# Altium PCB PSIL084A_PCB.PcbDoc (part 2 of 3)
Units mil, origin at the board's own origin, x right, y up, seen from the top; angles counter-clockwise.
Board outline 8750 x 2700 mil, 4 copper layers (Top Layer, Signal Layer 1, Signal Layer 2, Bottom Layer), stack 61.2 mil thick; 274 components, 214 nets, 1279 pads, 354 vias.
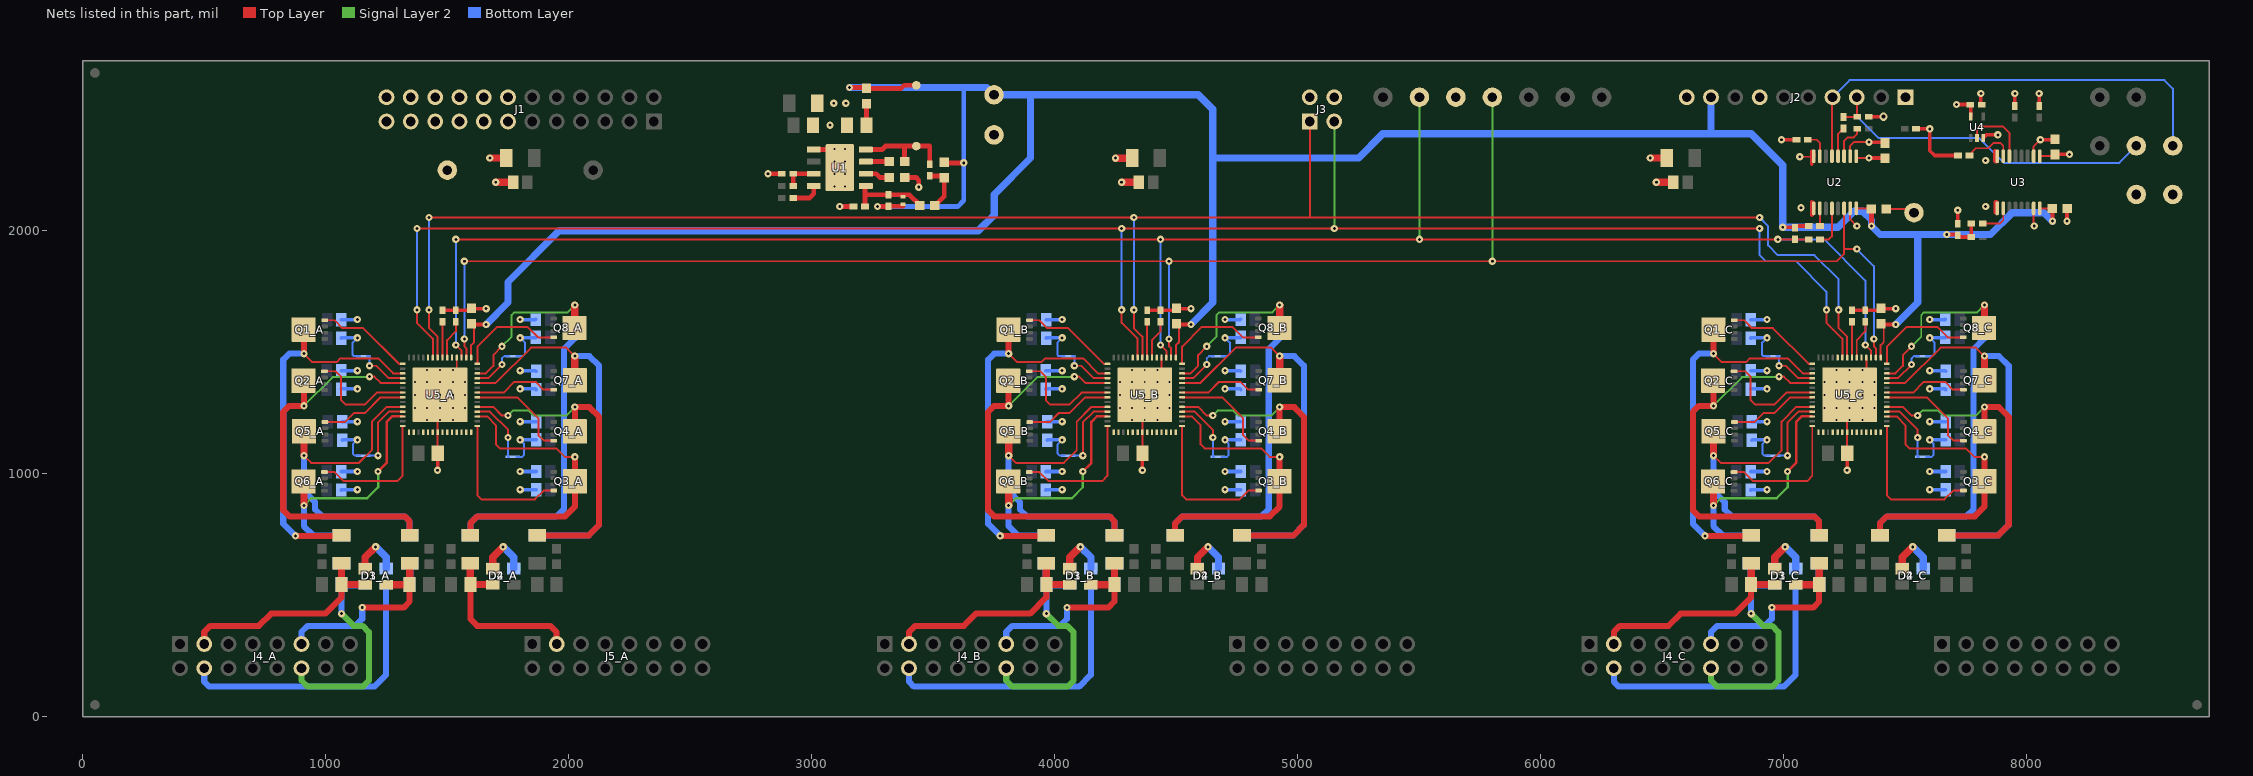
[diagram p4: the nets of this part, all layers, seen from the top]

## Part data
C1: library part CMP-0750039-1, "CAP, CERM, 0.01 µF, 50 V,+/- 10%, X7R, 0603", Cap_Case=0603, Manufacturer="Wurth Elektronik", TempCo=X7R, Tolerance_%=10%, Value2=50V, ValueDisplayed=0.01µF
C2: library part CMP-0007210-4, "CAP, CERM, 3300 pF, 50 V, +/- 5%, C0G/NP0, 0603", Cap_Case=0603, Manufacturer=MuRata, Supplier Part Number 1=GRM1885C1H332JA01D-ND, TempCo=C0G/NP0, Tolerance_%=5%, Value1=Unknown, Value2=50V, ValueDisplayed=3300pF
C3: library part CMP-0086511-1, "120pF ±1% 50V Ceramic Capacitor C0G, NP0 0402 (1005 Metric)", Manufacturer=Murata, TempCo=30ppm/°C, Tolerance_%=1%
C4 C17_A C17_B C17_C C18 C20_A C20_B C20_C C21_A C21_B C21_C C22_A C22_B C22_C C23_A C23_B C23_C C24_A C24_B C24_C C25_A C25_B C25_C C26_A C26_B C26_C C27_A C27_B C27_C C28 C30: library part CMP-0007886-2, "CAP, CERM, 0.1 uF, 100 V, +/- 10%, X7R, 0805", Cap_Case=0805, Manufacturer=TDK, Supplier Part Number 1=445-1418-1-ND, TempCo=X7R, Tolerance_%=10%, Value1="0.020726 ohm", Value2=100V, ValueDisplayed=0.1uF
C5 C9 C10 C11 C12 C16_A C16_B C16_C: library part CMP-0006837-4, "CAP, CERM, 0.1 uF, 50 V, +/- 10%, X7R, 0603", Cap_Case=0603, Manufacturer="Wurth Elektronik", TempCo=X7R, Tolerance_%=10%, Value1=Unknown, Value2=50V, ValueDisplayed=0.1uF
C6 C15 C19 C29: library part CMP-0750040-1, "CAP, CERM, 1 µF, 100 V,+/- 10%, X7R, AEC-Q200 Grade 1, 1206", Cap_Case=1206, Manufacturer=MuRata, TempCo=X7R, Tolerance_%=10%, Value2=100V, ValueDisplayed=1µF
C7: library part CMP-0007691-2, "CAP, CERM, 10 uF, 10 V, +/- 10%, X7R, 0805", Cap_Case=0805, Manufacturer="Wurth Elektronik", Supplier Part Number 1=710-885012207026, TempCo=X7R, Tolerance_%=10%, Value1=Unknown, Value2=10V, ValueDisplayed=10uF
C8: library part CMP-0082012-1, "CAP, CERM, 1 µF, 16 V,+/- 20%, X7R, 0603", Cap_Case=0603, Manufacturer=Samsung, Supplier Part Number 1=1276-6524-1-ND, TempCo=X7R, Tolerance_%=20%, Value2=16V, ValueDisplayed=1µF
C13 C14: library part CMP-0006227-2, "CAP, CERM, 0.01 uF, 16 V, +/- 10%, X7R, 0402", Cap_Case=0402, Manufacturer="Wurth Elektronik", Supplier Part Number 1=710-885012205031, TempCo=X7R, Tolerance_%=10%, Value1=Unknown, Value2=16V, ValueDisplayed=0.01uF
D1_A D1_B D1_C D2_A D2_B D2_C D3_A D3_B D3_C D4_A D4_B D4_C: library part CMP-0002018-2, "ESD Suppressor Diode Arrays, 7V, SMD", Manufacturer=Bourns, Supplier Part Number 1=CD143A-SR70CT-ND
F1_A F1_B F1_C F2_A F2_B F2_C F3_A F3_B F3_C F4_A F4_B F4_C F5_A F5_B F5_C F6_A F6_B F6_C F7_A F7_B F7_C F8_A F8_B F8_C: library part CMP-0003587-2, "Fuse, 1.5 A, 63VAC/VDC, SMD", Irating_A=1.5A, Manufacturer="Bel Fuse", Supplier Part Number 1=507-1188-1-ND
FID1 FID2 FID3 FID4 FID5 FID6: library part CMP-0077181-1, "Fiducial mark.  There is nothing to buy or mount.", Manufacturer=N/A
J1: library part CMP-0075423-1, "Header, 100mil, 12x2, Gold, TH", Color=Black, Current_A=6.3A, Manufacturer=Samtec, Supplier Part Number 1=SAM1028-12-ND, Voltage_V=550V
J2: library part CMP-0075422-1, "Header, 100mil, 10x1, Gold, TH", Color=Black, Current_A=6.3A, Manufacturer=Samtec, Supplier Part Number 1=SAM1029-10-ND, Voltage_V=550V
J3: library part CMP-0075404-1, "Header, 100mil, 2x2, Gold, TH", Color=Black, Current_A=6.3A, Manufacturer=Samtec, Supplier Part Number 1=SAM1028-02-ND, Voltage_V=550V
J4_A J4_B J4_C J5_A J5_B J5_C: library part CMP-0075418-1, "Header, 100mil, 8x2, Gold, TH", Color=Black, Current_A=6.3A, Manufacturer=Samtec, Supplier Part Number 1=SAM1028-08-ND, Voltage_V=550V
L1: library part CMP-0064704-3, "Inductor, Shielded Drum Core, Ferrite, 150 uH, 0.36 A, 0.605 ohm, SMD", Manufacturer="Wurth Elektronik", Supplier Part Number 1=732-3679-1-ND, Value1="0.605 ohm", Value2=0.36A, ValueDisplayed=150uH
L2_A L2_B L2_C L3_A L3_B L3_C L4_A L4_B L4_C L5_A L5_B L5_C L6_A L6_B L6_C L7_A L7_B L7_C L8_A L8_B L8_C L9_A L9_B L9_C: library part CMP-0078795-1, "Ferrite Bead, 600 ohm @ 100 MHz, 1 A, 0603", Manufacturer=TDK, Supplier Part Number 1=445-172898-1-ND, Value1="0.15 ohm", Value2=1A, ValueDisplayed="600 ohm"
LBL1: library part CMP-0003625-1, "Thermal Transfer Printable Labels, 0.650\" W x 0.200\" H - 10,000 per roll", Manufacturer=Brady, Supplier Part Number 1=97C5133
Logo1: library part CMP-0074838-1, "Texas Instrument Corporate Signature"
Logo2: library part CMP-0074844-1
Logo3: library part CMP-0074847-1, "FCC_disclaimer"
Logo4: library part CMP-0074769-1
NT_A1_A NT_A1_B NT_A1_C NT_B1_A NT_B1_B NT_B1_C NT_C1_A NT_C1_B NT_C1_C NT_D1_A NT_D1_B NT_D1_C: library part CMP-0078142-2, "Single point connection between nets.", Manufacturer=N/A
Q1_A Q1_B Q1_C Q2_A Q2_B Q2_C Q3_A Q3_B Q3_C Q4_A Q4_B Q4_C Q5_A Q5_B Q5_C Q6_A Q6_B Q6_C Q7_A Q7_B Q7_C Q8_A Q8_B Q8_C: library part CMP-0000969-3, "MOSFET, N-CH, 100 V, 5 A, DNH0008A (VSONP-8)", Alternate Manufacturer=None, Manufacturer="Texas Instruments", Value2="7.2 nC"
R1: library part CMP-0026021-3, "RES, 150 k, 1%, 0.063 W, AEC-Q200 Grade 0, 0402", Manufacturer=Vishay-Dale, Power_W=63mW, Supplier Part Number 1=541-150KLCT-ND, TempCo="100 ppm/C", Tolerance_%=1%, Value2=0.063W, Value_Code=150k
R2: library part CMP-0025950-3, "RES, 100 k, 1%, 0.063 W, AEC-Q200 Grade 0, 0402", Manufacturer=Vishay-Dale, Power_W=63mW, Supplier Part Number 1=541-100KLCT-ND, TempCo="100 ppm/C", Tolerance_%=1%, Value2=0.063W, Value_Code=100k
R3 R8 R14 R17 R18: library part CMP-0025958-3, "RES, 10.0 k, 1%, 0.063 W, AEC-Q200 Grade 0, 0402", Manufacturer=Vishay-Dale, Power_W=63mW, Supplier Part Number 1=541-10.0KLCT-ND, TempCo="100 ppm/C", Tolerance_%=1%, Value2=0.063W, Value_Code=10k0, ValueDisplayed=10.0k
R4: library part CMP-0025999-3, "RES, 133 k, 1%, 0.063 W, AEC-Q200 Grade 0, 0402", Manufacturer=Vishay-Dale, Power_W=63mW, Supplier Part Number 1=541-133KLCT-ND, TempCo="100 ppm/C", Tolerance_%=1%, Value2=0.063W, Value_Code=133k
R5: library part CMP-0025885-5, "RES, 0, 5%, 0.1 W, 0603", Manufacturer=Yageo, Power_W=100mW, Supplier Part Number 1=311-0.0GRCT-ND, TempCo="200 ppm/C", Tolerance_%=5%, Value2=0.1W, Value_Code=0000, ValueDisplayed=0
R6: library part CMP-0026340-2, "RES, 3.92 k, 1%, 0.063 W, AEC-Q200 Grade 0, 0402", Manufacturer=Vishay-Dale, Power_W=63mW, Supplier Part Number 1=541-3.92KLCT-ND, TempCo="100 ppm/C", Tolerance_%=1%, Value2=0.063W, Value_Code=3k92, ValueDisplayed=3.92k
R7: library part CMP-0026512-2, "RES, 6.04 k, 1%, 0.063 W, AEC-Q200 Grade 0, 0402", Manufacturer=Vishay-Dale, Power_W=63mW, Supplier Part Number 1=541-6.04KLCT-ND, TempCo="100 ppm/C", Tolerance_%=1%, Value2=0.063W, Value_Code=6k04, ValueDisplayed=6.04k
R9 R13 R15 R16 R37 R38: library part CMP-0026938-5, "RES, 4.7 k, 5%, 0.063 W, AEC-Q200 Grade 0, 0402", Manufacturer=Vishay-Dale, Power_W=63mW, Supplier Part Number 1=541-4.7KJCT-ND, TempCo="200 ppm/C", Tolerance_%=5%, Value2=0.063W, Value_Code=4k70, ValueDisplayed=4.7k
R10 R11 R12 R19_A R19_B R19_C R20_A R20_B R20_C: library part CMP-0026992-3, "RES, 0, 5%, 0.1 W, AEC-Q200 Grade 0, 0402", Manufacturer=Panasonic, Power_W=100mW, Supplier Part Number 1=P0.0JCT-ND, TempCo="600 ppm/C", Tolerance_%=5%, Value2=0.1W, Value_Code=0000, ValueDisplayed=0
R21_A R21_B R21_C R22_A R22_B R22_C R23_A R23_B R23_C R24_A R24_B R24_C R25_A R25_B R25_C R26_A R26_B R26_C R27_A R27_B R27_C R28_A R28_B R28_C R29_A R29_B R29_C R30_A R30_B R30_C R31_A R31_B R31_C R32_A R32_B R32_C R33_A R33_B R33_C R34_A R34_B R34_C R35_A R35_B R35_C R36_A R36_B R36_C: library part CMP-0021516-2, "RES, 0.51, 1%, 0.25 W, 0805", Manufacturer=Bourns, Power_W=250mW, Supplier Part Number 1=652-CRM0805FXR510ELF, TempCo="100 ppm/C", Tolerance_%=1%, Value2=0.25W, Value_Code=R510, ValueDisplayed=0.51
SH-J1 SH-J2: library part CMP-0003642-1, "Shunt, 100mil, Flash Gold, Black", Manufacturer="Sullins Connector Solutions", Supplier Part Number 1=S9001-ND
TP1 TP2 TP5: library part CMP-0055137-1, "Test Point, Miniature, Red, TH", Color=Red, Manufacturer=Keystone, PartNumber=5000, Supplier Part Number 1=36-5000-ND
TP3 TP4 TP14 TP15 TP19: library part CMP-0055138-1, "Test Point, Miniature, Black, TH", Color=Black, Manufacturer=Keystone, PartNumber=5001, Supplier Part Number 1=36-5001-ND
TP6 TP7 TP8 TP9 TP10: library part CMP-0055140-1, "Test Point, Miniature, Orange, TH", Color=Orange, Manufacturer=Keystone, PartNumber=5003, Supplier Part Number 1=36-5003-ND
TP11 TP12 TP13 TP16 TP17 TP18: library part CMP-0055139-1, "Test Point, Miniature, White, TH", Color=White, Manufacturer=Keystone, PartNumber=5002, Supplier Part Number 1=36-5002-ND
U1: library part CMP-0066086-2, "7.5-100V Wide Vin, 600mA Constant On-Time Synchronous Buck Regulator, DDA0008B (SOIC-8)", Alternate Manufacturer="Texas Instruments", Alternate PartNumber=LM5017MR/NOPB
U2: library part CMP-0078720-1, "High Speed, Robust EMC Triple-Channel Digital Isolators, DBQ0016A (SSOP-16)", Alternate Manufacturer="Texas Instruments", Alternate PartNumber=ISO7731FDBQR
U3: library part CMP-0013040-3, "High Speed, Robust EMC Quad-Channel Digital Isolators, DBQ0016A (SSOP-16)", Alternate Manufacturer="Texas Instruments", Alternate PartNumber=ISO7741DBQ
U4: library part CMP-0051390-2, "Single Buffer/Driver With Open-Drain Output, DCK0005A, LARGE T&R", F @ Nom Voltage(Max)(Mhz)=150, Generic Part Number=SN74LVC1G07, ICC @ Nom Voltage(Max)(mA)=0.01, Manufacturer="Texas Instruments", Operating Temperature Range(C)="-40 to 125,-40 to 85", Rating=Catalog, tpd @ Nom Voltage(Max)(ns)=8.6,6,4.7,4, Voltage(Nom)(V)=1.8,2.5,3.3,5
U5_A U5_B U5_C: library part CMP-0014018-5, "IEEE 802.3at 8-Port Power-over-Ethernet PSE, RTQ0056E (VQFN-56)", Alternate Manufacturer="Texas Instruments", Alternate PartNumber=TPS2388RTQT
ZZ1: library part CMP-0003616-3
ZZ2: library part CMP-0077236-1
ZZ3: library part CMP-0077237-1
ZZ4: library part CMP-0077238-1
ZZ5: library part CMP-0077238-1, "DO NOT TRIM CONNECTOR PINS on J5"

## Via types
v1: diameter 30, hole 12, Top Layer to Bottom Layer, 282 vias
v2: diameter 19.68, hole 7.87, Top Layer to Bottom Layer, 67 vias
v3: diameter 19.68, hole 7.87, Top Layer to Bottom Layer, tented both sides, 4 vias
v4: diameter 34, hole 16, Top Layer to Bottom Layer, 1 vias

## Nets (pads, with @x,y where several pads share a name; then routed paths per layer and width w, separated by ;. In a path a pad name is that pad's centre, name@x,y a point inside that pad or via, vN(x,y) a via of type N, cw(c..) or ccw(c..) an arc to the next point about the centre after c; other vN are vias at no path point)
3.3V_ISO: C9.1 C11.1 C14.2 J2.1 R8.1 R13.2 R17.1 R18.1 R38.2 TP5.1 U2.1 U3.1 U4.5 | length 796.1
  Top Layer w8: U2.1@7297.5,2307.28 7297.5,2302.5 7300,2300 v1(7350,2300) ; U3.1@8052.5,2307.28 8108.11,2307.28 C11.1@8115,2314.17
  Top Layer w15: v1(6990,2375) R13.2@7051.38,2375 ; v1(7350,2300) 7413.5,2300 C9.1@7415,2298.5 ; R8.1@7543.62,2420 v1(7600,2420) 7600,2330 7620,2310 R38.2@7720.31,2310 ; v1(7710,2520) 7766.31,2520 7768.82,2517.49 U4.5@7768.82,2470 ; R17.1@7950,2513.62 v1(7950,2565) ; R18.1@8050,2513.62 v1(8050,2565) ; C11.1@8115,2314.17 8115.83,2315 v1(8175,2315)
\PSE_INT: R9.1 R12.2 TP13.1 U5_A.45 U5_B.45 U5_C.45 | length 7900.5
  Top Layer w8: v1(1535,1530) 1558.58,1506.42 U5_A.45@1558.58,1478.54 ; v1(1535,1965) v1(4435,1965) v1(5500,1965) v1(6975,1965) R9.1@7045,1965 R12.2@7101.38,1965 ; v1(4435,1530) 4458.58,1506.42 U5_B.45@4458.58,1478.54 ; v1(7335,1530) 7358.58,1506.42 U5_C.45@7358.58,1478.54
  Signal Layer 2 w8: v1(5500,1965) TP13.1@5500,2550
  Bottom Layer w8: v1(1535,1530) v1(1535,1965) ; v1(4435,1530) v1(4435,1965) ; v1(6975,1965) 7165,1965 7335,1795 v1(7335,1530)
\PSE_RESET_A: TP11.1 U2.14 U5_A.44 U5_B.44 U5_C.44 | length 7883.8
  Top Layer w8: v1(1570,1555) 1570,1525 1578.27,1516.73 U5_A.44@1578.27,1478.54 ; v1(1570,1875) v1(4470,1875) v1(5800,1875) 7217.5,1875 7247.5,1905 7247.5,1925 ; v1(4470,1555) 4470,1525 4478.27,1516.73 U5_B.44@4478.27,1478.54 ; U2.14@7247.5,2092.72 7247.5,1925 ; v1(7300,1925) 7247.5,1925 ; v1(7370,1555) 7370,1525 7378.27,1516.73 U5_C.44@7378.27,1478.54
  Signal Layer 2 w8: v1(5800,1875) TP11.1@5800,2550
  Bottom Layer w8: v1(1570,1555) v1(1570,1875) ; v1(4470,1555) v1(4470,1875) ; v1(7300,1925) 7370,1855 v1(7370,1555)
GND: C4.1 C6.1 C7.2 C8.2 C10.2 C12.2 C13.1 C15.1 C16_A.2 C16_B.2 C16_C.2 C17_A.2 C17_B.2 C17_C.2 C18.1 C19.1 C28.1 C29.1 C30.1 D1_A.1 D1_B.1 D1_C.1 D2_A.1 D2_B.1 D2_C.1 D3_A.1 D3_B.1 D3_C.1 D4_A.1 D4_B.1 D4_C.1 J1.13 J1.14 J1.15 J1.16 J1.17 J1.18 J1.19 J1.20 J1.21 J1.22 J1.23 J1.24 J2.10 J3.2 J3.4 NT_A1_A.1 NT_A1_B.1 NT_A1_C.1 NT_B1_A.2 NT_B1_B.2 NT_B1_C.2 NT_C1_A.2 NT_C1_B.2 NT_C1_C.2 NT_D1_A.2 NT_D1_B.2 NT_D1_C.2 R6.2 R7.2 R19_A.2 R19_B.2 R19_C.2 R20_A.2 R20_B.2 R20_C.2 R21_A.2 R21_B.2 R21_C.2 R22_A.2 R22_B.2 R22_C.2 R23_A.2 R23_B.2 R23_C.2 R24_A.2 R24_B.2 R24_C.2 R25_A.2 R25_B.2 R25_C.2 R26_A.2 R26_B.2 R26_C.2 R27_A.2 R27_B.2 R27_C.2 R28_A.2 R28_B.2 R28_C.2 R29_A.2 R29_B.2 R29_C.2 R30_A.2 R30_B.2 R30_C.2 R31_A.2 R31_B.2 R31_C.2 R32_A.2 R32_B.2 R32_C.2 R33_A.2 R33_B.2 R33_C.2 R34_A.2 R34_B.2 R34_C.2 R35_A.2 R35_B.2 R35_C.2 R36_A.2 R36_B.2 R36_C.2 TP3.1 TP4.1 TP14.1 TP19.1 U1.1 U1.9@3115,2260 U2.9 U2.15 U3.9 U3.15 U5_A.21 U5_A.46 U5_A.57@1470,1325 U5_B.21 U5_B.46 U5_B.57@4370,1325 U5_C.21 U5_C.46 U5_C.57@7270,1325 | length 9109.2
  Top Layer w8: C17_A.2@1460.16,1085.63 U5_A.21@1460.16,1171.46 1460.16,1315.16 v2(1470,1325) v2(1523.15,1378.15) 1538.9,1393.9 U5_A.46@1538.9,1478.54 ; C17_B.2@4360.16,1085.63 U5_B.21@4360.16,1171.46 4360.16,1315.16 v2(4370,1325) v2(4423.15,1378.15) 4438.9,1393.9 U5_B.46@4438.9,1478.54 ; C17_C.2@7260.16,1085.63 U5_C.21@7260.16,1171.46 7260.16,1315.16 v2(7270,1325) v2(7323.15,1378.15) 7338.9,1393.9 U5_C.46@7338.9,1478.54 ; U2.15@7272.5,2092.72 7272.5,2047.5 v1(7300,2020) ; C10.2@7421.5,2090 7520,2090 TP19.1@7535,2075 ; U3.15@8027.5,2092.72 8027.5,2022.5 v1(8030,2020)
  Top Layer w15: v1(1460,1015) 1460,1085.47 C17_A.2@1460.16,1085.63 ; R20_A.2@1480,1673.62 R19_A.2@1535,1673.62 1592.13,1673.62 C16_A.2@1600,1681.5 1601.5,1680 v1(1660,1680) ; v1(4360,1015) 4360,1085.47 C17_B.2@4360.16,1085.63 ; R20_B.2@4380,1673.62 R19_B.2@4435,1673.62 4492.13,1673.62 C16_B.2@4500,1681.5 4501.5,1680 v1(4560,1680) ; 7115,2065 7115,2120 7122.5,2112.5 U2.9@7122.5,2092.72 ; v1(7260,1015) 7260,1085.47 C17_C.2@7260.16,1085.63 ; R20_C.2@7280,1673.62 R19_C.2@7335,1673.62 7392.13,1673.62 C16_C.2@7400,1681.5 7401.5,1680 v1(7460,1680) ; C13.1@7715,2024.68 v1(7715,2085) ; U3.9@7870,2075 7870,2120 7875,2120 7877.5,2117.5 U3.9@7877.5,2092.72 ; C12.2@8162.56,2092.72 8165,2090.28 v1(8165,2040)
  Top Layer w20: v1(2820,2235) R6.2@2876.38,2235 ; U1.1@3007.72,2335 3115,2335 U1.9@3115,2260 ; v1(3115,2100) R7.2@3171.38,2100 ; C8.2@3381.5,2220 3428.5,2220 3440,2208.5 v1(3440,2180)
  Top Layer w30: D1_A.1@1161.69,610.43 1161.69,656.69 v1(1205,700) ; v1(1675,2300) C19.1@1746.85,2300 ; D2_A.1@1686.69,610.43 1686.69,656.69 v1(1730,700) ; v1(1699.21,2200) C18.1@1770.47,2200 ; D1_B.1@4061.69,610.43 4061.69,656.69 v1(4105,700) ; v1(4249.92,2299.21) 4321.06,2299.21 C29.1@4321.85,2300 ; v1(4275,2200) C28.1@4345.47,2200 ; D2_B.1@4586.69,610.43 4586.69,656.69 v1(4630,700) ; v1(6450,2300) C15.1@6521.85,2300 ; v1(6475,2200) C30.1@6545.47,2200 ; D1_C.1@6961.69,610.43 6961.69,656.69 v1(7005,700) ; D2_C.1@7486.69,610.43 7486.69,656.69 v1(7530,700)
  Bottom Layer w8: v1(1130,1140) 1111.26,1121.26 1111.26,1083.74 1120,1075 NT_B1_A.2@1140,1075 ; v1(1130,1560) 1110,1540 1110,1490 1115,1485 NT_A1_A.1@1140,1485 ; NT_C1_A.2@1785,1070 1807.56,1070 1815,1077.44 1815,1125 v1(1800,1140) ; NT_D1_A.2@1785,1485 1810,1485 1820,1495 1820,1540 v1(1800,1560) ; v1(4030,1140) 4011.26,1121.26 4011.26,1083.74 4020,1075 NT_B1_B.2@4040,1075 ; v1(4030,1560) 4010,1540 4010,1490 4015,1485 NT_A1_B.1@4040,1485 ; NT_C1_B.2@4685,1070 4707.56,1070 4715,1077.44 4715,1125 v1(4700,1140) ; NT_D1_B.2@4685,1485 4710,1485 4720,1495 4720,1540 v1(4700,1560) ; v1(6930,1140) 6911.26,1121.26 6911.26,1083.74 6920,1075 NT_B1_C.2@6940,1075 ; v1(6930,1560) 6910,1540 6910,1490 6915,1485 NT_A1_C.1@6940,1485 ; NT_C1_C.2@7585,1070 7607.56,1070 7615,1077.44 7615,1125 v1(7600,1140) ; NT_D1_C.2@7585,1485 7610,1485 7620,1495 7620,1540 v1(7600,1560)
  Bottom Layer w15: R32_A.2@1063.09,933.92 1064.17,935 v1(1130,935) ; R31_A.2@1063.09,1008.92 1064.17,1010 v1(1130,1010) ; R24_A.2@1063.09,1348.92 1064.17,1350 v1(1130,1350) ; R23_A.2@1063.09,1423.92 1064.17,1425 v1(1130,1425) ; R22_A.2@1064.19,1558.92 1065.28,1560 v1(1130,1560) ; R21_A.2@1064.19,1633.92 1128.92,1633.92 v1(1130,1635) ; R30_A.2@1068.09,1138.92 1069.17,1140 v1(1130,1140) ; R29_A.2@1068.09,1213.92 1069.17,1215 v1(1130,1215) ; v1(1800,935) R26_A.2@1865.08,935 ; v1(1800,1010) R25_A.2@1865.08,1010 ; v1(1800,1140) R28_A.2@1865.08,1140 ; v1(1800,1215) R27_A.2@1865.08,1215 ; v1(1800,1350) 1862.46,1350 R34_A.2@1865.08,1347.39 ; v1(1800,1425) 1862.46,1425 R33_A.2@1865.08,1422.39 ; v1(1800,1560) 1862.48,1560 R36_A.2@1863.98,1561.5 ; v1(1800,1635) 1862.48,1635 R35_A.2@1863.98,1636.5 ; R32_B.2@3963.09,933.92 3964.17,935 v1(4030,935) ; R31_B.2@3963.09,1008.92 3964.17,1010 v1(4030,1010) ; R24_B.2@3963.09,1348.92 3964.17,1350 v1(4030,1350) ; R23_B.2@3963.09,1423.92 3964.17,1425 v1(4030,1425) ; R22_B.2@3964.19,1558.92 3965.28,1560 v1(4030,1560) ; R21_B.2@3964.19,1633.92 4028.92,1633.92 v1(4030,1635) ; R30_B.2@3968.09,1138.92 3969.17,1140 v1(4030,1140) ; R29_B.2@3968.09,1213.92 3969.17,1215 v1(4030,1215) ; v1(4700,935) R26_B.2@4765.08,935 ; v1(4700,1010) R25_B.2@4765.08,1010 ; v1(4700,1140) R28_B.2@4765.08,1140 ; v1(4700,1215) R27_B.2@4765.08,1215 ; v1(4700,1350) 4762.46,1350 R34_B.2@4765.08,1347.39 ; v1(4700,1425) 4762.46,1425 R33_B.2@4765.08,1422.39 ; v1(4700,1560) 4762.48,1560 R36_B.2@4763.98,1561.5 ; v1(4700,1635) 4762.48,1635 R35_B.2@4763.98,1636.5 ; R32_C.2@6863.09,933.92 6864.17,935 v1(6930,935) ; R31_C.2@6863.09,1008.92 6864.17,1010 v1(6930,1010) ; R24_C.2@6863.09,1348.92 6864.17,1350 v1(6930,1350) ; R23_C.2@6863.09,1423.92 6864.17,1425 v1(6930,1425) ; R22_C.2@6864.19,1558.92 6865.28,1560 v1(6930,1560) ; R21_C.2@6864.19,1633.92 6928.92,1633.92 v1(6930,1635) ; R30_C.2@6868.09,1138.92 6869.17,1140 v1(6930,1140) ; R29_C.2@6868.09,1213.92 6869.17,1215 v1(6930,1215) ; v1(7600,935) R26_C.2@7665.08,935 ; v1(7600,1010) R25_C.2@7665.08,1010 ; v1(7600,1140) R28_C.2@7665.08,1140 ; v1(7600,1215) R27_C.2@7665.08,1215 ; v1(7600,1350) 7662.46,1350 R34_C.2@7665.08,1347.39 ; v1(7600,1425) 7662.46,1425 R33_C.2@7665.08,1422.39 ; v1(7600,1560) 7662.48,1560 R36_C.2@7663.98,1561.5 ; v1(7600,1635) 7662.48,1635 R35_C.2@7663.98,1636.5
  Bottom Layer w30: v1(1205,700) 1248.31,656.69 D3_A.1@1248.31,610.43 ; v1(1730,700) 1773.31,656.69 D4_A.1@1773.31,610.43 ; v1(4105,700) 4148.31,656.69 D3_B.1@4148.31,610.43 ; v1(4630,700) 4673.31,656.69 D4_B.1@4673.31,610.43 ; v1(7005,700) 7048.31,656.69 D3_C.1@7048.31,610.43 ; v1(7530,700) 7573.31,656.69 D4_C.1@7573.31,610.43
  other v1: 7070,2095 7830,2100 3075,2435 3090,2525 3140,2525
  other v2: 1416.85,1222.64 1470,1222.64 1523.15,1222.64 4316.85,1222.64 4370,1222.64 4423.15,1222.64 7216.85,1222.64 7270,1222.64 7323.15,1222.64 1367.64,1271.85 1416.85,1271.85 1470,1271.85 1523.15,1271.85 1572.36,1271.85 4267.64,1271.85 4316.85,1271.85 4370,1271.85 4423.15,1271.85 4472.36,1271.85 7167.64,1271.85 7216.85,1271.85 7270,1271.85 7323.15,1271.85 7372.36,1271.85 1367.64,1325 1416.85,1325 1523.15,1325 1572.36,1325 4267.64,1325 4316.85,1325 4423.15,1325 4472.36,1325 7167.64,1325 7216.85,1325 7323.15,1325 7372.36,1325 1367.64,1378.15 1416.85,1378.15 1470,1378.15 1572.36,1378.15 4267.64,1378.15 4316.85,1378.15 4370,1378.15 4472.36,1378.15 7167.64,1378.15 7216.85,1378.15 7270,1378.15 7372.36,1378.15 1416.85,1427.36 1470,1427.36 1523.15,1427.36 4316.85,1427.36 4370,1427.36 4423.15,1427.36 7216.85,1427.36 7270,1427.36 7323.15,1427.36 3093.35,2234.41 3136.65,2234.41 3093.35,2285.59 3136.65,2285.59
  other v3: 3093.35,2183.23 3136.65,2183.23 3093.35,2336.77 3136.65,2336.77
GND_ISO: C9.2 C11.2 C14.1 J2.7 R14.2 TP15.1 U2.2 U2.8 U3.2 U3.8 U4.3 | length 711.4
  Top Layer w8: v1(7065,2305) 7115,2305 U2.8@7120.22,2305 ; U2.2@7272.5,2307.28 7272.5,2350.3 7287.2,2365 v1(7350,2365) ; U3.2@8027.5,2307.28 8027.5,2347.5 v1(8055,2375)
  Top Layer w15: 7114.37,2328.19 U2.8@7115,2327.56 ; 7115,2275 7115,2305 U2.8@7115,2327.56 ; U2.8@7122.5,2307.28 7122.5,2320.06 U2.8@7115,2327.56 ; R14.2@7348.62,2470 v4(7410,2470) ; v1(7350,2365) 7411.5,2365 C9.2@7415,2361.5 ; C14.1@7809.69,2518.99 7810,2519.3 v1(7810,2565) ; U4.3@7820,2381.42 7833.58,2395 v1(7880,2395) ; 7868.52,2329.62 7868.52,2287.73 7872.52,2283.73 7877.5,2288.71 U3.8@7877.5,2307.28 ; v1(8055,2375) 8112.83,2375 C11.2@8115,2377.17
  other v1: 7830,2290
INT: J2.4 TP8.1 U2.5 | length 1922.2
  Top Layer w8: U2.5@7197.5,2307.28 7197.5,2547.5 J2.4@7200,2550
  Bottom Layer w8: J2.4@7200,2550 7270,2620 8565,2620 8600,2585 TP8.1@8600,2350
NetC1_1: C1.1 L1.1 R4.1 U1.8 | length 409.4
  Top Layer w20: U1.8@3222.28,2335 3289.17,2335 3303.19,2349.02 3385,2349.02 ; C1.1@3381.5,2285 3381.5,2345.51 3385,2349.02 ; R4.1@3485,2273.62 3485,2349.02 L1.1@3430,2349.02 3385,2349.02
NetC1_2: C1.2 U1.7 | length 96.2
  Top Layer w20: U1.7@3222.28,2285 C1.2@3318.5,2285
NetC2_2: C2.2 C5.1 R4.2 | length 192.1
  Top Layer w20: R4.2@3485,2226.38 3537.13,2226.38 C2.2@3545,2218.5 3545,2142.05 C5.1@3507.95,2105
NetC3_2: C3.2 C5.2 R3.2 R7.1 U1.5 | length 331.5
  Top Layer w20: R7.1@3218.62,2100 3218.62,2150 ; U1.5@3222.28,2185 3218.62,2181.34 3218.62,2150 ; C5.2@3444.96,2105 3401.34,2148.62 3375,2148.62 R3.2@3315,2148.62 3220,2148.62 3218.62,2150
NetC7_1: C7.1 R5.2 | length 88.5
  Top Layer w20: C7.1@3225,2435 R5.2@3225,2523.5
NetC8_1: C8.1 U1.6 | length 102.4
  Top Layer w20: U1.6@3222.28,2235 3265,2235 3280,2220 C8.1@3318.5,2220
NetNT_A1_A_2: NT_A1_A.2 U5_A.4 | length 207.6
  Top Layer w8: v1(1180,1445) 1207.93,1445 1259.03,1393.9 U5_A.4@1316.46,1393.9
  Bottom Layer w8: NT_A1_A.2@1170,1485 1180,1485 v1(1180,1445)
NetNT_A1_B_2: NT_A1_B.2 U5_B.4 | length 207.6
  Top Layer w8: v1(4080,1445) 4107.93,1445 4159.03,1393.9 U5_B.4@4216.46,1393.9
  Bottom Layer w8: NT_A1_B.2@4070,1485 4080,1485 v1(4080,1445)
NetNT_A1_C_2: NT_A1_C.2 U5_C.4 | length 207.6
  Top Layer w8: v1(6980,1445) 7007.93,1445 7059.03,1393.9 U5_C.4@7116.46,1393.9
  Bottom Layer w8: NT_A1_C.2@6970,1485 6980,1485 v1(6980,1445)
NetNT_B1_A_1: NT_B1_A.1 U5_A.11 | length 301.6
  Top Layer w8: v1(1215,1075) 1215,1211.85 1259.25,1256.1 U5_A.11@1316.46,1256.1
  Bottom Layer w8: NT_B1_A.1@1170,1075 v1(1215,1075)
NetNT_B1_B_1: NT_B1_B.1 U5_B.11 | length 301.6
  Top Layer w8: v1(4115,1075) 4115,1211.85 4159.25,1256.1 U5_B.11@4216.46,1256.1
  Bottom Layer w8: NT_B1_B.1@4070,1075 v1(4115,1075)
NetNT_B1_C_1: NT_B1_C.1 U5_C.11 | length 301.6
  Top Layer w8: v1(7015,1075) 7015,1211.85 7059.25,1256.1 U5_C.11@7116.46,1256.1
  Bottom Layer w8: NT_B1_C.1@6970,1075 v1(7015,1075)
NetNT_C1_A_1: NT_C1_A.1 U5_A.32 | length 274
  Top Layer w8: U5_A.32@1623.54,1256.1 1675.63,1256.1 1750,1181.73 v1(1750,1150)
  Bottom Layer w8: v1(1750,1150) 1750,1070 NT_C1_A.1@1755,1070
NetNT_C1_B_1: NT_C1_B.1 U5_B.32 | length 274
  Top Layer w8: U5_B.32@4523.54,1256.1 4575.63,1256.1 4650,1181.73 v1(4650,1150)
  Bottom Layer w8: v1(4650,1150) 4650,1070 NT_C1_B.1@4655,1070
NetNT_C1_C_1: NT_C1_C.1 U5_C.32 | length 274
  Top Layer w8: U5_C.32@7423.54,1256.1 7475.63,1256.1 7550,1181.73 v1(7550,1150)
  Bottom Layer w8: v1(7550,1150) 7550,1070 NT_C1_C.1@7555,1070
NetNT_D1_A_1: NT_D1_A.1 U5_A.39 | length 183.8
  Top Layer w8: U5_A.39@1623.54,1393.9 1668.9,1393.9 v1(1725,1450)
  Bottom Layer w8: v1(1725,1450) 1725,1474.94 1735.06,1485 NT_D1_A.1@1755,1485
NetNT_D1_B_1: NT_D1_B.1 U5_B.39 | length 183.8
  Top Layer w8: U5_B.39@4523.54,1393.9 4568.9,1393.9 v1(4625,1450)
  Bottom Layer w8: v1(4625,1450) 4625,1474.94 4635.06,1485 NT_D1_B.1@4655,1485
NetNT_D1_C_1: NT_D1_C.1 U5_C.39 | length 183.8
  Top Layer w8: U5_C.39@7423.54,1393.9 7468.9,1393.9 v1(7525,1450)
  Bottom Layer w8: v1(7525,1450) 7525,1474.94 7535.06,1485 NT_D1_C.1@7555,1485
NetR1_2: R1.2 U1.4 | length 123.7
  Top Layer w20: R1.2@2923.62,2135 2990,2135 3007.72,2152.72 U1.4@3007.72,2185
NetR2_2: R2.2 R6.1 U1.3 | length 134.1
  Top Layer w20: R2.2@2923.62,2185 R6.1@2923.62,2235 U1.3@3007.72,2235
NetR10_2: R10.2 U2.3 | length 149.5
  Top Layer w8: U2.3@7247.5,2307.28 7247.5,2370.57 7261.93,2385 7286.65,2385 7301.38,2399.72 R10.2@7301.38,2420
NetR11_2: R11.2 U2.4 | length 123.4
  Top Layer w8: U2.4@7222.5,2307.28 7222.5,2398.88 R11.2@7245,2421.38
NetR12_1: R12.1 U2.12 | length 169.3
  Top Layer w8: R12.1@7148.62,1965 7185,1965 7197.5,1977.5 U2.12@7197.5,2092.72
NetR13_1: R13.1 U2.7 | length 109.3
  Top Layer w8: R13.1@7098.62,2375 7135,2375 7147.5,2362.5 U2.7@7147.5,2307.28
NetR15_2: R15.2 U2.10 | length 73.2
  Top Layer w8: U2.10@7147.5,2092.72 7147.5,2021.12 R15.2@7148.62,2020
NetR19_A_1: R19_A.1 U5_A.48 | length 162.5
  Top Layer w8: U5_A.48@1499.53,1478.54 1499.53,1550.83 1535,1586.3 R19_A.1@1535,1626.38
NetR19_B_1: R19_B.1 U5_B.48 | length 162.5
  Top Layer w8: U5_B.48@4399.53,1478.54 4399.53,1550.83 4435,1586.3 R19_B.1@4435,1626.38
NetR19_C_1: R19_C.1 U5_C.48 | length 162.5
  Top Layer w8: U5_C.48@7299.53,1478.54 7299.53,1550.83 7335,1586.3 R19_C.1@7335,1626.38
NetR20_A_1: R20_A.1 U5_A.49 | length 147.9
  Top Layer w8: U5_A.49@1479.84,1478.54 1479.84,1626.22 R20_A.1@1480,1626.38
NetR20_B_1: R20_B.1 U5_B.49 | length 147.9
  Top Layer w8: U5_B.49@4379.84,1478.54 4379.84,1626.22 R20_B.1@4380,1626.38
NetR20_C_1: R20_C.1 U5_C.49 | length 147.9
  Top Layer w8: U5_C.49@7279.84,1478.54 7279.84,1626.22 R20_C.1@7280,1626.38
NetR37_1: R37.1 U3.10 | length 138.3
  Top Layer w8: R37.1@7818.62,2030 7888.35,2030 7902.5,2044.15 U3.10@7902.5,2092.72
NetR38_1: R38.1 U3.7 | length 212.5
  Top Layer w8: R38.1@7759.68,2310 7789.68,2340 7840,2340 7862.5,2362.5 7890,2362.5 7902.5,2350 U3.7@7902.5,2307.28
NetU3_6: U3.6 U4.2 | length 279.9
  Top Layer w8: U4.2@7794.41,2381.42 7794.41,2415 7809.41,2430 7900.71,2430 7927.5,2403.21 U3.6@7927.5,2307.28
NetU5_A_15: U5_A.15
NetU5_A_16: U5_A.16
NetU5_A_18: U5_A.18
NetU5_A_19: U5_A.19
NetU5_A_20: U5_A.20
NetU5_A_22: U5_A.22
NetU5_A_23: U5_A.23
NetU5_A_24: U5_A.24
NetU5_A_25: U5_A.25
NetU5_A_26: U5_A.26
NetU5_A_27: U5_A.27
NetU5_A_28: U5_A.28
NetU5_A_47: U5_A.47
NetU5_A_52: U5_A.52
NetU5_B_15: U5_B.15
NetU5_B_16: U5_B.16
NetU5_B_18: U5_B.18
NetU5_B_19: U5_B.19
NetU5_B_20: U5_B.20
NetU5_B_22: U5_B.22
NetU5_B_23: U5_B.23
NetU5_B_24: U5_B.24
NetU5_B_25: U5_B.25
NetU5_B_26: U5_B.26
NetU5_B_27: U5_B.27
NetU5_B_28: U5_B.28
NetU5_B_47: U5_B.47
NetU5_B_52: U5_B.52
NetU5_C_15: U5_C.15
NetU5_C_16: U5_C.16
NetU5_C_18: U5_C.18
NetU5_C_19: U5_C.19
NetU5_C_20: U5_C.20
NetU5_C_22: U5_C.22
NetU5_C_23: U5_C.23
NetU5_C_24: U5_C.24
NetU5_C_25: U5_C.25
NetU5_C_26: U5_C.26
NetU5_C_27: U5_C.27
NetU5_C_28: U5_C.28
NetU5_C_47: U5_C.47
NetU5_C_52: U5_C.52
OSS: J2.3 R11.1 R14.1 TP7.1 | length 1474.4
  Top Layer w8: R11.1@7245,2468.62 7300,2468.62 R14.1@7301.38,2470 7301.38,2548.62 J2.3@7300,2550
  Bottom Layer w8: J2.3@7300,2550 7300,2471.38 7389.96,2381.42 7803.35,2381.42 7904.76,2280 8380,2280 TP7.1@8450,2350
PSE_3.3V: C2.1 C3.1 C10.1 C12.1 C13.2 C16_A.1 C16_B.1 C16_C.1 J2.9 L1.2 R3.1 R5.1 R9.2 R15.1 R16.2 R37.2 TP1.1 U2.16 U3.16 U5_A.43 U5_B.43 U5_C.43 | length 12261
  Top Layer w8: U5_A.43@1597.95,1478.54 1597.95,1529.76 1610.75,1542.56 1610.75,1607.76 C16_A.1@1603.5,1615 ; U5_B.43@4497.95,1478.54 4497.95,1529.76 4510.75,1542.56 4510.75,1607.76 C16_B.1@4503.5,1615 ; U2.16@7297.5,2092.72 C10.1@7355.79,2092.72 ; U5_C.43@7397.95,1478.54 7397.95,1529.76 7410.75,1542.56 7410.75,1607.76 C16_C.1@7403.5,1615 ; U3.16@8052.5,2092.72 C12.1@8107.44,2092.72
  Top Layer w15: C16_A.1@1600,1618.5 1603.5,1615 v1(1660,1615) ; C16_B.1@4500,1618.5 4503.5,1615 v1(4560,1615) ; v1(6995,2015) 7041.38,2015 7046.38,2020 R15.1@7101.38,2020 ; C16_C.1@7400,1618.5 7403.5,1615 v1(7460,1615) ; v1(7670,1985) 7670.31,1985.31 7715,1985.31 7725.31,1975 R16.2@7771.38,1975 R37.2@7771.38,2030 ; R37.2@7771.38,2021.06 R37.2@7775.31,2025 ; v1(8105,2040) 8105,2090.28 C12.1@8107.44,2092.72
  Top Layer w20: v1(3155,2590) 3221.5,2590 R5.1@3225,2586.5 3367.51,2586.5 3380.03,2599.02 L1.2@3430,2599.02 ; v1(3270,2100) 3313.62,2100 R3.1@3315,2101.38 C3.1@3375,2101.38 ; C2.1@3545,2281.5 3546.5,2280 v1(3625,2280) ; C10.1@7355.79,2092.72 C10.1@7358.5,2090 7360,2088.5 v1(7360,2020)
  Bottom Layer w20: v1(3270,2100) 3600,2100 3625,2125 v1(3625,2280) 3625,2590
  Bottom Layer w30: v1(1660,1615) 1750,1705 1750,1790 1960,2000 3685,2000 3750,2065 3750,2150 3900,2300 3900,2560 ; v1(3155,2590) 3625,2590 3720,2590 TP1.1@3750,2560 3900,2560 ; v1(4560,1615) 4650,1705 4650,2300 ; J2.9@6700,2550 6700,2399.72 ; 6995,2075 v1(6995,2015) 7222.5,2015 7288.49,2080.99 7324.01,2080.99 7360,2045 v1(7360,2020) 7395,1985 7550,1985 ; 6995,2080.99 6995,2270 6865.28,2399.72 6700,2399.72 ; v1(7460,1615) 7550,1705 7550,1985 ; v1(8105,2040) 8070,2075 7940,2075 7850,1985 v1(7670,1985) 7550,1985 ; 3900,2560 4590,2560 4650,2500 4650,2300 ; 4650,2300 5250,2300 5349.72,2399.72 6700,2399.72
PSE_A3_A: J3.1 U5_A.50 U5_B.50 U5_C.50 | length 7865.5
  Top Layer w8: v1(1425,1675) 1425,1600 1460.16,1564.84 U5_A.50@1460.16,1478.54 ; v1(1425,2055) v1(4325,2055) 5050,2055 ; v1(4325,1675) 4325,1600 4360.16,1564.84 U5_B.50@4360.16,1478.54 ; J3.1@5050,2450 5050,2055 ; v1(6900,2055) 5050,2055 ; v1(7225,1675) 7225,1600 7260.16,1564.84 U5_C.50@7260.16,1478.54
  Bottom Layer w8: v1(1425,1675) v1(1425,2055) ; v1(4325,1675) v1(4325,2055) ; v1(6900,2055) 6935,2020 6935,1940 6975,1900 7125,1900 7225,1800 v1(7225,1675)
PSE_A4_A: J3.3 U5_A.51 U5_B.51 U5_C.51 | length 7827.9
  Top Layer w8: v1(1375,1675) 1375,1621.81 1440.47,1556.34 U5_A.51@1440.47,1478.54 ; v1(1375,2010) v1(4275,2010) v1(5150,2010) v1(6900,2010) ; v1(4275,1675) 4275,1621.81 4340.47,1556.34 U5_B.51@4340.47,1478.54 ; v1(7175,1675) 7175,1621.81 7240.47,1556.34 U5_C.51@7240.47,1478.54
  Signal Layer 2 w8: v1(5150,2010) J3.3@5150,2450
  Bottom Layer w8: v1(1375,1675) v1(1375,2010) ; v1(4275,1675) v1(4275,2010) ; v1(6900,2010) 6900,1900 6925,1875 7050,1875 7175,1750 v1(7175,1675)
PSE_D1_A: F1_A.2 Q1_A.5 Q1_A.6 Q1_A.7 Q1_A.8 Q1_A.9@909.27,1593.92 U5_A.3 | length 1583.8
  Top Layer w8: v1(910,1495) 945,1460 1044.59,1460 1059.59,1475 1215.93,1475 1277.34,1413.58 U5_A.3@1316.46,1413.58
  Top Layer w25: v1(875,745) 1062.91,745 F1_A.2@1065,747.09 ; Q1_A.9@909.27,1593.92 910,1593.19 v1(910,1495)
  Bottom Layer w25: v1(875,745) 825,795 825,1470 850,1495 v1(910,1495)
PSE_D1_B: F1_B.2 Q1_B.5 Q1_B.6 Q1_B.7 Q1_B.8 Q1_B.9@3809.27,1593.92 U5_B.3 | length 1583.8
  Top Layer w8: v1(3810,1495) 3845,1460 3944.59,1460 3959.59,1475 4115.93,1475 4177.34,1413.58 U5_B.3@4216.46,1413.58
  Top Layer w25: v1(3775,745) 3962.91,745 F1_B.2@3965,747.09 ; Q1_B.9@3809.27,1593.92 3810,1593.19 v1(3810,1495)
  Bottom Layer w25: v1(3775,745) 3725,795 3725,1470 3750,1495 v1(3810,1495)
PSE_D1_C: F1_C.2 Q1_C.5 Q1_C.6 Q1_C.7 Q1_C.8 Q1_C.9@6709.27,1593.92 U5_C.3 | length 1583.8
  Top Layer w8: v1(6710,1495) 6745,1460 6844.59,1460 6859.59,1475 7015.93,1475 7077.34,1413.58 U5_C.3@7116.46,1413.58
  Top Layer w25: v1(6675,745) 6862.91,745 F1_C.2@6865,747.09 ; Q1_C.9@6709.27,1593.92 6710,1593.19 v1(6710,1495)
  Bottom Layer w25: v1(6675,745) 6625,795 6625,1470 6650,1495 v1(6710,1495)
PSE_D2_A: F2_A.2 Q2_A.5 Q2_A.6 Q2_A.7 Q2_A.8 Q2_A.9@908.17,1383.92 U5_A.5 | length 1668.4
  Top Layer w8: v1(1180,1400) 1200,1400 1225.79,1374.21 U5_A.5@1316.46,1374.21
  Top Layer w25: Q2_A.9@908.17,1383.92 910,1382.09 v1(910,1280) 850,1280 825,1255 825,850 850,825 1325,825 1345,805 F2_A.2@1345,747.09
  Signal Layer 2 w8: v1(910,1280) 1028.13,1398.13 1178.13,1398.13 v1(1180,1400)
PSE_D2_B: F2_B.2 Q2_B.5 Q2_B.6 Q2_B.7 Q2_B.8 Q2_B.9@3808.17,1383.92 U5_B.5 | length 1668.4
  Top Layer w8: v1(4080,1400) 4100,1400 4125.79,1374.21 U5_B.5@4216.46,1374.21
  Top Layer w25: Q2_B.9@3808.17,1383.92 3810,1382.09 v1(3810,1280) 3750,1280 3725,1255 3725,850 3750,825 4225,825 4245,805 F2_B.2@4245,747.09
  Signal Layer 2 w8: v1(3810,1280) 3928.13,1398.13 4078.13,1398.13 v1(4080,1400)
PSE_D2_C: F2_C.2 Q2_C.5 Q2_C.6 Q2_C.7 Q2_C.8 Q2_C.9@6708.17,1383.92 U5_C.5 | length 1668.4
  Top Layer w8: v1(6980,1400) 7000,1400 7025.79,1374.21 U5_C.5@7116.46,1374.21
  Top Layer w25: Q2_C.9@6708.17,1383.92 6710,1382.09 v1(6710,1280) 6650,1280 6625,1255 6625,850 6650,825 7125,825 7145,805 F2_C.2@7145,747.09
  Signal Layer 2 w8: v1(6710,1280) 6828.13,1398.13 6978.13,1398.13 v1(6980,1400)
PSE_D3_A: F5_A.2 Q5_A.5 Q5_A.6 Q5_A.7 Q5_A.8 Q5_A.9@910,1175 U5_A.10 | length 1390.1
  Top Layer w8: v1(910,1075) 940,1045 1136.69,1045 1190,1098.31 1190,1215 1250.79,1275.79 U5_A.10@1316.46,1275.79
  Top Layer w30: v1(910,1075) Q5_A.9@910,1175
  Bottom Layer w25: v1(910,1075) 910,930 956.46,883.54 956.46,853.54 985,825 1325,825 1345,805 F5_A.2@1345,747.09
PSE_D3_B: F5_B.2 Q5_B.5 Q5_B.6 Q5_B.7 Q5_B.8 Q5_B.9@3810,1175 U5_B.10 | length 1390.1
  Top Layer w8: v1(3810,1075) 3840,1045 4036.69,1045 4090,1098.31 4090,1215 4150.79,1275.79 U5_B.10@4216.46,1275.79
  Top Layer w30: v1(3810,1075) Q5_B.9@3810,1175
  Bottom Layer w25: v1(3810,1075) 3810,930 3856.46,883.54 3856.46,853.54 3885,825 4225,825 4245,805 F5_B.2@4245,747.09
PSE_D3_C: F5_C.2 Q5_C.5 Q5_C.6 Q5_C.7 Q5_C.8 Q5_C.9@6710,1175 U5_C.10 | length 1390.1
  Top Layer w8: v1(6710,1075) 6740,1045 6936.69,1045 6990,1098.31 6990,1215 7050.79,1275.79 U5_C.10@7116.46,1275.79
  Top Layer w30: v1(6710,1075) Q5_C.9@6710,1175
  Bottom Layer w25: v1(6710,1075) 6710,930 6756.46,883.54 6756.46,853.54 6785,825 7125,825 7145,805 F5_C.2@7145,747.09
PSE_D4_A: F6_A.2 Q6_A.5 Q6_A.6 Q6_A.7 Q6_A.8 Q6_A.9@908.17,968.92 U5_A.12 | length 1050.6
  Top Layer w10: v1(1215,1010) 1250,1045 1250,1213.92 1272.5,1236.42 U5_A.12@1316.46,1236.42
  Top Layer w30: Q6_A.9@908.17,968.92 910,967.09 v1(910,870)
  Signal Layer 2 w10: v1(910,870) 940,900 1170,900 1215,945 v1(1215,1010)
  Bottom Layer w25: v1(910,870) 910,785 947.91,747.09 F6_A.2@1065,747.09
PSE_D4_B: F6_B.2 Q6_B.5 Q6_B.6 Q6_B.7 Q6_B.8 Q6_B.9@3808.17,968.92 U5_B.12 | length 1050.6
  Top Layer w10: v1(4115,1010) 4150,1045 4150,1213.92 4172.5,1236.42 U5_B.12@4216.46,1236.42
  Top Layer w30: Q6_B.9@3808.17,968.92 3810,967.09 v1(3810,870)
  Signal Layer 2 w10: v1(3810,870) 3840,900 4070,900 4115,945 v1(4115,1010)
  Bottom Layer w25: v1(3810,870) 3810,785 3847.91,747.09 F6_B.2@3965,747.09
PSE_D4_C: F6_C.2 Q6_C.5 Q6_C.6 Q6_C.7 Q6_C.8 Q6_C.9@6708.17,968.92 U5_C.12 | length 1050.6
  Top Layer w10: v1(7015,1010) 7050,1045 7050,1213.92 7072.5,1236.42 U5_C.12@7116.46,1236.42
  Top Layer w30: Q6_C.9@6708.17,968.92 6710,967.09 v1(6710,870)
  Signal Layer 2 w10: v1(6710,870) 6740,900 6970,900 7015,945 v1(7015,1010)
  Bottom Layer w25: v1(6710,870) 6710,785 6747.91,747.09 F6_C.2@6865,747.09
PSE_D5_A: F3_A.2 Q3_A.5 Q3_A.6 Q3_A.7 Q3_A.8 Q3_A.9@2025,970 U5_A.31 | length 1229.1
  Top Layer w8: U5_A.31@1623.54,1236.42 1663.58,1236.42 1700,1200 1700,1121.5 1716.5,1105 1949,1105 1984,1070 v1(2025,1070)
  Top Layer w25: F3_A.2@1595,747.09 1595,796.46 1623.54,825 1985,825 2025,865 Q3_A.9@2025,970 v1(2025,1070)
PSE_D5_B: F3_B.2 Q3_B.5 Q3_B.6 Q3_B.7 Q3_B.8 Q3_B.9@4925,970 U5_B.31 | length 1229.1
  Top Layer w8: U5_B.31@4523.54,1236.42 4563.58,1236.42 4600,1200 4600,1121.5 4616.5,1105 4849,1105 4884,1070 v1(4925,1070)
  Top Layer w25: F3_B.2@4495,747.09 4495,796.46 4523.54,825 4885,825 4925,865 Q3_B.9@4925,970 v1(4925,1070)
PSE_D5_C: F3_C.2 Q3_C.5 Q3_C.6 Q3_C.7 Q3_C.8 Q3_C.9@7825,970 U5_C.31 | length 1229.1
  Top Layer w8: U5_C.31@7423.54,1236.42 7463.58,1236.42 7500,1200 7500,1121.5 7516.5,1105 7749,1105 7784,1070 v1(7825,1070)
  Top Layer w25: F3_C.2@7395,747.09 7395,796.46 7423.54,825 7785,825 7825,865 Q3_C.9@7825,970 v1(7825,1070)
PSE_D6_A: F4_A.2 Q4_A.5 Q4_A.6 Q4_A.7 Q4_A.8 Q4_A.9@2025,1175 U5_A.33 | length 1381.7
  Top Layer w8: U5_A.33@1623.54,1275.79 1689.21,1275.79 1725.06,1239.94 v1(1750,1239.94)
  Top Layer w25: F4_A.2@1870,747.09 2082.09,747.09 2125,790 2125,1235 2085,1275 v1(2025,1275) Q4_A.9@2025,1175
  Signal Layer 2 w8: v1(1750,1239.94) 1770.06,1260 1834.84,1260 1854.84,1240 1990,1240 v1(2025,1275)
PSE_D6_B: F4_B.2 Q4_B.5 Q4_B.6 Q4_B.7 Q4_B.8 Q4_B.9@4925,1175 U5_B.33 | length 1381.7
  Top Layer w8: U5_B.33@4523.54,1275.79 4589.21,1275.79 4625.06,1239.94 v1(4650,1239.94)
  Top Layer w25: F4_B.2@4770,747.09 4982.09,747.09 5025,790 5025,1235 4985,1275 v1(4925,1275) Q4_B.9@4925,1175
  Signal Layer 2 w8: v1(4650,1239.94) 4670.06,1260 4734.84,1260 4754.84,1240 4890,1240 v1(4925,1275)
PSE_D6_C: F4_C.2 Q4_C.5 Q4_C.6 Q4_C.7 Q4_C.8 Q4_C.9@7825,1175 U5_C.33 | length 1381.7
  Top Layer w8: U5_C.33@7423.54,1275.79 7489.21,1275.79 7525.06,1239.94 v1(7550,1239.94)
  Top Layer w25: F4_C.2@7670,747.09 7882.09,747.09 7925,790 7925,1235 7885,1275 v1(7825,1275) Q4_C.9@7825,1175
  Signal Layer 2 w8: v1(7550,1239.94) 7570.06,1260 7634.84,1260 7654.84,1240 7790,1240 v1(7825,1275)
PSE_D7_A: F7_A.2 Q7_A.5 Q7_A.6 Q7_A.7 Q7_A.8 Q7_A.9@2025,1385 U5_A.38 | length 1620.7
  Top Layer w8: U5_A.38@1623.54,1374.21 1699.21,1374.21 1845,1520 1990,1520 v1(2025,1485)
  Top Layer w30: Q7_A.9@2025,1385 v1(2025,1485)
  Bottom Layer w25: F7_A.2@1870,747.09 2082.09,747.09 2125,790 2125,1445 2085,1485 v1(2025,1485)
PSE_D7_B: F7_B.2 Q7_B.5 Q7_B.6 Q7_B.7 Q7_B.8 Q7_B.9@4925,1385 U5_B.38 | length 1620.7
  Top Layer w8: U5_B.38@4523.54,1374.21 4599.21,1374.21 4745,1520 4890,1520 v1(4925,1485)
  Top Layer w30: Q7_B.9@4925,1385 v1(4925,1485)
  Bottom Layer w25: F7_B.2@4770,747.09 4982.09,747.09 5025,790 5025,1445 4985,1485 v1(4925,1485)
PSE_D7_C: F7_C.2 Q7_C.5 Q7_C.6 Q7_C.7 Q7_C.8 Q7_C.9@7825,1385 U5_C.38 | length 1620.7
  Top Layer w8: U5_C.38@7423.54,1374.21 7499.21,1374.21 7645,1520 7790,1520 v1(7825,1485)
  Top Layer w30: Q7_C.9@7825,1385 v1(7825,1485)
  Bottom Layer w25: F7_C.2@7670,747.09 7882.09,747.09 7925,790 7925,1445 7885,1485 v1(7825,1485)
PSE_D8_A: F8_A.2 Q8_A.5 Q8_A.6 Q8_A.7 Q8_A.8 Q8_A.9@2023.9,1600.48 U5_A.40 | length 2008.6
  Top Layer w8: U5_A.40@1623.54,1413.58 1658.58,1413.58 1689.21,1444.21 1689.21,1489.21 v1(1725,1525)
  Top Layer w30: Q8_A.9@2023.9,1600.48 2025,1601.58 v1(2025,1695)
  Signal Layer 2 w8: v1(1725,1525) 1765,1565 1765,1653.78 1776.24,1665.02 1995.02,1665.02 v1(2025,1695)
  Bottom Layer w25: F8_A.2@1595,747.09 1595,796.46 1623.54,825 1950,825 1980,855 1980,1512.6 2025,1557.6 v1(2025,1695)
PSE_D8_B: F8_B.2 Q8_B.5 Q8_B.6 Q8_B.7 Q8_B.8 Q8_B.9@4923.9,1600.48 U5_B.40 | length 2008.6
  Top Layer w8: U5_B.40@4523.54,1413.58 4558.58,1413.58 4589.21,1444.21 4589.21,1489.21 v1(4625,1525)
  Top Layer w30: Q8_B.9@4923.9,1600.48 4925,1601.58 v1(4925,1695)
  Signal Layer 2 w8: v1(4625,1525) 4665,1565 4665,1653.78 4676.24,1665.02 4895.02,1665.02 v1(4925,1695)
  Bottom Layer w25: F8_B.2@4495,747.09 4495,796.46 4523.54,825 4850,825 4880,855 4880,1512.6 4925,1557.6 v1(4925,1695)
PSE_D8_C: F8_C.2 Q8_C.5 Q8_C.6 Q8_C.7 Q8_C.8 Q8_C.9@7823.9,1600.48 U5_C.40 | length 2008.6
  Top Layer w8: U5_C.40@7423.54,1413.58 7458.58,1413.58 7489.21,1444.21 7489.21,1489.21 v1(7525,1525)
  Top Layer w30: Q8_C.9@7823.9,1600.48 7825,1601.58 v1(7825,1695)
  Signal Layer 2 w8: v1(7525,1525) 7565,1565 7565,1653.78 7576.24,1665.02 7795.02,1665.02 v1(7825,1695)
  Bottom Layer w25: F8_C.2@7395,747.09 7395,796.46 7423.54,825 7750,825 7780,855 7780,1512.6 7825,1557.6 v1(7825,1695)
PSE_G1_A: Q1_A.4 U5_A.1 | length 395.1
  Top Layer w8: Q1_A.4@995.69,1632.3 1036.28,1632.3 1068.58,1600 1154.21,1600 1301.26,1452.95 U5_A.1@1316.46,1452.95
PSE_G1_B: Q1_B.4 U5_B.1 | length 395.1
  Top Layer w8: Q1_B.4@3895.69,1632.3 3936.28,1632.3 3968.58,1600 4054.21,1600 4201.26,1452.95 U5_B.1@4216.46,1452.95
PSE_G1_C: Q1_C.4 U5_C.1 | length 395.1
  Top Layer w8: Q1_C.4@6795.69,1632.3 6836.28,1632.3 6868.58,1600 6954.21,1600 7101.26,1452.95 U5_C.1@7116.46,1452.95
PSE_G2_A: Q2_A.4 U5_A.7 | length 455.3
  Top Layer w8: Q2_A.4@994.59,1422.3 1040,1422.3 1063.09,1399.21 1063.09,1303.78 1081.87,1285 1160,1285 1209.84,1334.84 U5_A.7@1316.46,1334.84
PSE_G2_B: Q2_B.4 U5_B.7 | length 455.3
  Top Layer w8: Q2_B.4@3894.59,1422.3 3940,1422.3 3963.09,1399.21 3963.09,1303.78 3981.87,1285 4060,1285 4109.84,1334.84 U5_B.7@4216.46,1334.84
PSE_G2_C: Q2_C.4 U5_C.7 | length 455.3
  Top Layer w8: Q2_C.4@6794.59,1422.3 6840,1422.3 6863.09,1399.21 6863.09,1303.78 6881.87,1285 6960,1285 7009.84,1334.84 U5_C.7@7116.46,1334.84
PSE_G3_A: Q5_A.4 U5_A.8 | length 362.2
  Top Layer w8: Q5_A.4@996.42,1213.39 1078.39,1213.39 1115,1250 1160,1250 1225.16,1315.16 U5_A.8@1316.46,1315.16
PSE_G3_B: Q5_B.4 U5_B.8 | length 362.2
  Top Layer w8: Q5_B.4@3896.42,1213.39 3978.39,1213.39 4015,1250 4060,1250 4125.16,1315.16 U5_B.8@4216.46,1315.16
PSE_G3_C: Q5_C.4 U5_C.8 | length 362.2
  Top Layer w8: Q5_C.4@6796.42,1213.39 6878.39,1213.39 6915,1250 6960,1250 7025.16,1315.16 U5_C.8@7116.46,1315.16
PSE_G4_A: Q6_A.4 U5_A.14 | length 551.8
  Top Layer w8: Q6_A.4@994.59,1007.3 1036.61,1007.3 1073.92,970 1295,970 1316.46,991.46 U5_A.14@1316.46,1197.05
PSE_G4_B: Q6_B.4 U5_B.14 | length 551.8
  Top Layer w8: Q6_B.4@3894.59,1007.3 3936.61,1007.3 3973.92,970 4195,970 4216.46,991.46 U5_B.14@4216.46,1197.05
PSE_G4_C: Q6_C.4 U5_C.14 | length 551.8
  Top Layer w8: Q6_C.4@6794.59,1007.3 6836.61,1007.3 6873.92,970 7095,970 7116.46,991.46 U5_C.14@7116.46,1197.05
PSE_G5_A: Q3_A.4 U5_A.29 | length 622.6
  Top Layer w8: U5_A.29@1623.54,1197.05 1623.54,911.46 1640,895 1860,895 1896.61,931.61 Q3_A.4@1938.58,931.61
PSE_G5_B: Q3_B.4 U5_B.29 | length 622.6
  Top Layer w8: U5_B.29@4523.54,1197.05 4523.54,911.46 4540,895 4760,895 4796.61,931.61 Q3_B.4@4838.58,931.61
PSE_G5_C: Q3_C.4 U5_C.29 | length 622.6
  Top Layer w8: U5_C.29@7423.54,1197.05 7423.54,911.46 7440,895 7660,895 7696.61,931.61 Q3_C.4@7738.58,931.61
PSE_G6_A: Q4_A.4 U5_A.35 | length 429.5
  Top Layer w8: U5_A.35@1623.54,1315.16 1788.52,1315.16 1875,1228.68 1875,1159.61 1897.99,1136.61 Q4_A.4@1938.58,1136.61
PSE_G6_B: Q4_B.4 U5_B.35 | length 429.5
  Top Layer w8: U5_B.35@4523.54,1315.16 4688.52,1315.16 4775,1228.68 4775,1159.61 4797.99,1136.61 Q4_B.4@4838.58,1136.61
PSE_G6_C: Q4_C.4 U5_C.35 | length 429.5
  Top Layer w8: U5_C.35@7423.54,1315.16 7588.52,1315.16 7675,1228.68 7675,1159.61 7697.99,1136.61 Q4_C.4@7738.58,1136.61
PSE_G7_A: Q7_A.4 U5_A.36 | length 346.6
  Top Layer w8: U5_A.36@1623.54,1334.84 1731.34,1334.84 1775.38,1378.88 1863.11,1378.88 1895.38,1346.61 Q7_A.4@1938.58,1346.61
PSE_G7_B: Q7_B.4 U5_B.36 | length 346.6
  Top Layer w8: U5_B.36@4523.54,1334.84 4631.34,1334.84 4675.38,1378.88 4763.11,1378.88 4795.38,1346.61 Q7_B.4@4838.58,1346.61
PSE_G7_C: Q7_C.4 U5_C.36 | length 346.6
  Top Layer w8: U5_C.36@7423.54,1334.84 7531.34,1334.84 7575.38,1378.88 7663.11,1378.88 7695.38,1346.61 Q7_C.4@7738.58,1346.61
PSE_G8_A: Q8_A.4 U5_A.42 | length 436.3
  Top Layer w8: U5_A.42@1623.54,1452.95 1623.54,1523.54 1705.37,1605.37 1829.94,1605.37 1873.22,1562.1 Q8_A.4@1937.48,1562.1
PSE_G8_B: Q8_B.4 U5_B.42 | length 436.3
  Top Layer w8: U5_B.42@4523.54,1452.95 4523.54,1523.54 4605.37,1605.37 4729.94,1605.37 4773.22,1562.1 Q8_B.4@4837.48,1562.1
PSE_G8_C: Q8_C.4 U5_C.42 | length 436.3
  Top Layer w8: U5_C.42@7423.54,1452.95 7423.54,1523.54 7505.37,1605.37 7629.94,1605.37 7673.22,1562.1 Q8_C.4@7737.48,1562.1
PSE_N1_A: C20_A.2 D1_A.2 F1_A.1 J4_A.3 | length 912.1
  Top Layer w25: J4_A.3@500,300 500,350 525,375 725,375 775,425 998.09,425 1065,491.91 C20_A.2@1065,545
  Top Layer w30: F1_A.1@1065,632.91 C20_A.2@1065,545 1160.2,545 D1_A.2@1161.69,543.5
PSE_N1_B: C20_B.2 D1_B.2 F1_B.1 J4_B.3 | length 912.1
  Top Layer w25: J4_B.3@3400,300 3400,350 3425,375 3625,375 3675,425 3898.09,425 3965,491.91 C20_B.2@3965,545
  Top Layer w30: F1_B.1@3965,632.91 C20_B.2@3965,545 4060.2,545 D1_B.2@4061.69,543.5
PSE_N1_C: C20_C.2 D1_C.2 F1_C.1 J4_C.3 | length 912.1
  Top Layer w25: J4_C.3@6300,300 6300,350 6325,375 6525,375 6575,425 6798.09,425 6865,491.91 C20_C.2@6865,545
  Top Layer w30: F1_C.1@6865,632.91 C20_C.2@6865,545 6960.2,545 D1_C.2@6961.69,543.5
PSE_N2_A: C21_A.2 D1_A.3 F2_A.1 J4_A.11 | length 829.4
  Top Layer w25: v1(1150,450) 1320,450 1345,475 C21_A.2@1345,545
  Top Layer w30: D1_A.3@1248.31,543.5 1343.5,543.5 C21_A.2@1345,545 F2_A.1@1345,632.91
  Bottom Layer w25: J4_A.11@900,300 900,350 925,375 1121.69,375 1150,403.31 v1(1150,450)
PSE_N2_B: C21_B.2 D1_B.3 F2_B.1 J4_B.11 | length 829.4
  Top Layer w25: v1(4050,450) 4220,450 4245,475 C21_B.2@4245,545
  Top Layer w30: D1_B.3@4148.31,543.5 4243.5,543.5 C21_B.2@4245,545 F2_B.1@4245,632.91
  Bottom Layer w25: J4_B.11@3800,300 3800,350 3825,375 4021.69,375 4050,403.31 v1(4050,450)
PSE_N2_C: C21_C.2 D1_C.3 F2_C.1 J4_C.11 | length 829.4
  Top Layer w25: v1(6950,450) 7120,450 7145,475 C21_C.2@7145,545
  Top Layer w30: D1_C.3@7048.31,543.5 7143.5,543.5 C21_C.2@7145,545 F2_C.1@7145,632.91
  Bottom Layer w25: J4_C.11@6700,300 6700,350 6725,375 6921.69,375 6950,403.31 v1(6950,450)
PSE_N3_A: C24_A.2 D3_A.2 F5_A.1 J4_A.4 | length 1387
  Bottom Layer w25: J4_A.4@500,200 500,145 520,125 1200,125 1248.31,173.31 D3_A.2@1248.31,543.5
  Bottom Layer w30: D3_A.2@1248.31,543.5 1249.8,545 C24_A.2@1345,545 F5_A.1@1345,632.91
PSE_N3_B: C24_B.2 D3_B.2 F5_B.1 J4_B.4 | length 1387
  Bottom Layer w25: J4_B.4@3400,200 3400,145 3420,125 4100,125 4148.31,173.31 D3_B.2@4148.31,543.5
  Bottom Layer w30: D3_B.2@4148.31,543.5 4149.8,545 C24_B.2@4245,545 F5_B.1@4245,632.91
PSE_N3_C: C24_C.2 D3_C.2 F5_C.1 J4_C.4 | length 1387
  Bottom Layer w25: J4_C.4@6300,200 6300,145 6320,125 7000,125 7048.31,173.31 D3_C.2@7048.31,543.5
  Bottom Layer w30: D3_C.2@7048.31,543.5 7049.8,545 C24_C.2@7145,545 F5_C.1@7145,632.91
PSE_N4_A: C25_A.2 D3_A.3 F6_A.1 J4_A.12 | length 996.4
  Signal Layer 2 w25: J4_A.12@900,200 900,150 925,125 1152.44,125 1177.44,150 1177.44,349.25 1151.69,375 1115,375 v1(1065,425)
  Bottom Layer w25: v1(1065,425) C25_A.2@1065,545
  Bottom Layer w30: F6_A.1@1065,632.91 C25_A.2@1065,545 1066.5,543.5 D3_A.3@1161.69,543.5
PSE_N4_B: C25_B.2 D3_B.3 F6_B.1 J4_B.12 | length 996.4
  Signal Layer 2 w25: J4_B.12@3800,200 3800,150 3825,125 4052.44,125 4077.44,150 4077.44,349.25 4051.69,375 4015,375 v1(3965,425)
  Bottom Layer w25: v1(3965,425) C25_B.2@3965,545
  Bottom Layer w30: F6_B.1@3965,632.91 C25_B.2@3965,545 3966.5,543.5 D3_B.3@4061.69,543.5
PSE_N4_C: C25_C.2 D3_C.3 F6_C.1 J4_C.12 | length 996.4
  Signal Layer 2 w25: J4_C.12@6700,200 6700,150 6725,125 6952.44,125 6977.44,150 6977.44,349.25 6951.69,375 6915,375 v1(6865,425)
  Bottom Layer w25: v1(6865,425) C25_C.2@6865,545
  Bottom Layer w30: F6_C.1@6865,632.91 C25_C.2@6865,545 6866.5,543.5 D3_C.3@6961.69,543.5
PSE_N5_A: C22_A.2 D2_A.2 F3_A.1 J5_A.3 | length 748.5
  Top Layer w25: C22_A.2@1595,545 1595,403.31 1623.31,375 1924.13,375 1950,349.13 J5_A.3@1950,300
  Top Layer w30: F3_A.1@1595,632.91 C22_A.2@1595,545 1685.2,545 D2_A.2@1686.69,543.5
